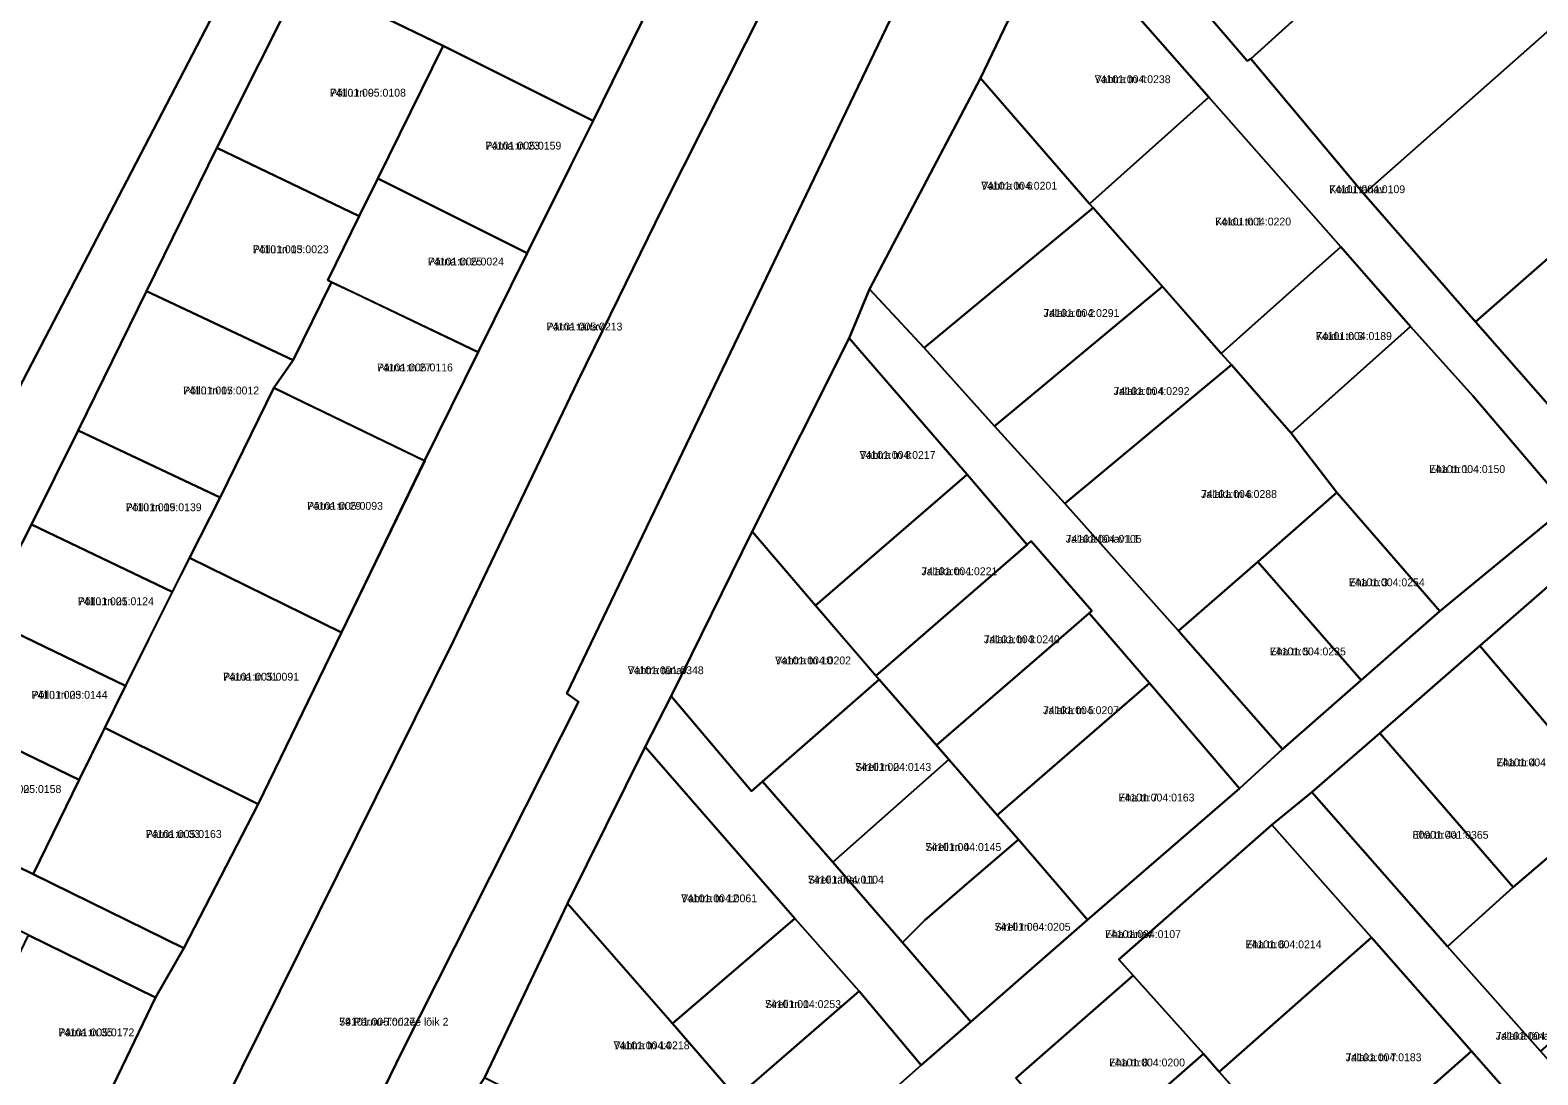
# Model space of a CAD drawing. Extents: x 524000 to 564260, y 6469338 to 6496391.
# Drawn here: x 537778.5 to 538066.5, y 6473057.4 to 6473256.9 of the extents above; entities that cross this region are included whole.
import ezdxf

# ---------------------------------------------------------------- set-up
doc = ezdxf.new("R2010")
doc.units = 0
for name, color, linetype in [('L_AADRESS', 7, 'Continuous'), ('PIIR', 7, 'Continuous'), ('TUNNUS', 7, 'Continuous')]:
    doc.layers.add(name, color=color, linetype=linetype)

msp = doc.modelspace()

# ---------------------------------------------------------------- linework, layer by layer
at = {"layer": 'PIIR'}
for points in [[(537911.45, 6473432.19), (537898.77, 6473405), (537878.24, 6473363.63), (537862.56, 6473331.9), (537846.66, 6473299.16), (537830.46, 6473267.01), (537814.16, 6473234.46), (537800.74, 6473207.08), (537787.69, 6473180.48), (537778.82, 6473162.48), (537769.71, 6473144.74), (537760.91, 6473126.77), (537752.14, 6473108.89), (537735.25, 6473107.1), (537744.18, 6473124.88), (537753.17, 6473143.42), (537772.14, 6473180.53), (537824.43, 6473280.98), (537842.16, 6473316.83), (537846.14, 6473325.5), (537858.94, 6473351.56), (537867.79, 6473369.49), (537901.08, 6473436.32)], [(537726.44, 6473156.95), (537699.68, 6473170.07), (537672.88, 6473183.77), (537646.08, 6473197.47), (537632.7, 6473204.36), (537624, 6473208.76), (537627.57, 6473215.35), (537724.12, 6473330.67), (537771.55, 6473307.16), (537797.54, 6473294.29), (537824.43, 6473280.98), (537772.14, 6473180.53), (537745.72, 6473193.99)], [(538037.45, 6473274.84), (538066.93, 6473300.55), (538088.99, 6473274.96), (538033.3, 6473225.67), (538011.66, 6473251.45)], [(537830.46, 6473267.01), (537846.66, 6473299.16), (537874.47, 6473287.9), (537902.82, 6473273.77), (537886.07, 6473239.61), (537857.45, 6473253.92)], [(538019.43, 6473296.1), (538037.45, 6473274.84), (538011.66, 6473251.45), (538011.01, 6473251.05), (537992.9, 6473272.24)], [(537979.58, 6473287.68), (537992.9, 6473272.24), (538011.01, 6473251.05), (538011.66, 6473251.45), (538033.3, 6473225.67), (538054.58, 6473201.22), (538079, 6473173.43), (538072.12, 6473165.95), (538054.09, 6473187.1), (538042.21, 6473200.34), (538028.86, 6473215.53), (538003.68, 6473244.12), (537974.33, 6473277.57)], [(537974.33, 6473277.57), (538003.68, 6473244.12), (537980.89, 6473223.78), (537960.04, 6473247.79)], [(538033.3, 6473225.67), (538088.99, 6473274.96), (538110.95, 6473250.31), (538070.39, 6473215.01), (538054.58, 6473201.22)], [(537830.46, 6473267.01), (537857.45, 6473253.92), (537844.93, 6473228.59), (537841.38, 6473221.39), (537814.16, 6473234.46)], [(537857.45, 6473253.92), (537886.07, 6473239.61), (537881.82, 6473231.11), (537873.44, 6473214.34), (537844.93, 6473228.59), (537853.2, 6473245.42)], [(537938.83, 6473207.45), (537960.04, 6473247.79), (537980.89, 6473223.78), (537981.55, 6473223.02), (537949.29, 6473196.28)], [(538006.05, 6473195.17), (537981.55, 6473223.02), (537980.89, 6473223.78), (538003.68, 6473244.12), (538028.86, 6473215.53)], [(537814.16, 6473234.46), (537841.38, 6473221.39), (537835.4, 6473209.21), (537836.11, 6473208.82), (537828.75, 6473193.88), (537800.74, 6473207.08)], [(537844.93, 6473228.59), (537873.44, 6473214.34), (537864.09, 6473195.4), (537836.11, 6473208.82), (537835.4, 6473209.21), (537841.38, 6473221.39)], [(537949.29, 6473196.28), (537981.55, 6473223.02), (537994.79, 6473207.97), (537962.73, 6473181.28)], [(538007.97, 6473192.99), (538006.05, 6473195.17), (538028.86, 6473215.53), (538042.21, 6473200.34), (538019.42, 6473179.98)], [(538054.58, 6473201.22), (538070.39, 6473215.01), (538088.51, 6473194.4), (538094.86, 6473187.09), (538079, 6473173.43)], [(537828.75, 6473193.88), (537836.11, 6473208.82), (537840.71, 6473206.61), (537864.09, 6473195.4), (537853.88, 6473174.7), (537830.42, 6473186.01), (537825.07, 6473188.59)], [(537938.83, 6473207.45), (537949.29, 6473196.28), (537962.73, 6473181.28), (537976.14, 6473166.52), (537997.9, 6473142.17), (538017.73, 6473119.59), (538009.53, 6473112.11), (537992.33, 6473132.2), (537980.78, 6473145.55), (537981.35, 6473146.04), (537969.75, 6473159.33), (537968.97, 6473158.65), (537957.48, 6473172.04), (537934.96, 6473198.12)], [(537976.14, 6473166.52), (537962.73, 6473181.28), (537994.79, 6473207.97), (538006.05, 6473195.17), (538007.97, 6473192.99)], [(537800.74, 6473207.08), (537828.75, 6473193.88), (537825.07, 6473188.59), (537814.81, 6473167.64), (537787.69, 6473180.48)], [(538019.42, 6473179.98), (538042.21, 6473200.34), (538054.09, 6473187.1), (538072.12, 6473165.95), (538047.81, 6473145.97), (538028.1, 6473168.59)], [(537916.45, 6473161.14), (537934.96, 6473198.12), (537957.48, 6473172.04), (537928.57, 6473147.02)], [(537976.14, 6473166.52), (538007.97, 6473192.99), (538019.42, 6473179.98), (538028.1, 6473168.59), (538013.01, 6473155.36), (537997.9, 6473142.17)], [(537814.81, 6473167.64), (537825.07, 6473188.59), (537853.89, 6473174.69), (537837.99, 6473141.9), (537808.95, 6473156.13)], [(537588.67, 6473182.04), (537601.13, 6473175.67), (537614.54, 6473168.87), (537627.92, 6473161.97), (537654.72, 6473148.27), (537681.52, 6473134.57), (537708.32, 6473120.87), (537735.25, 6473107.1), (537752.14, 6473108.89), (537779.08, 6473095.69), (537807.87, 6473081.6), (537802.47, 6473072.14), (537778.25, 6473084.07), (537753.6, 6473096.21), (537713.66, 6473101.96), (537679.62, 6473119.33), (537647.7, 6473135.08), (537617.7, 6473150.13), (537593.3, 6473162.73), (537575.4, 6473171.96), (537586.01, 6473183.4)], [(537787.69, 6473180.48), (537814.81, 6473167.64), (537808.95, 6473156.13), (537805.67, 6473149.63), (537778.82, 6473162.48)], [(537928.57, 6473147.02), (537954.29, 6473169.28), (537957.48, 6473172.04), (537968.97, 6473158.65), (537965.78, 6473155.89), (537940.06, 6473133.63)], [(538028.1, 6473168.59), (538047.81, 6473145.97), (538032.77, 6473132.78), (538013.01, 6473155.36)], [(537778.82, 6473162.48), (537805.67, 6473149.63), (537796.72, 6473131.69), (537769.71, 6473144.74)], [(537900.95, 6473129.73), (537916.45, 6473161.14), (537928.57, 6473147.02), (537940.68, 6473132.91), (537916.31, 6473111.59)], [(537940.68, 6473132.91), (537940.06, 6473133.63), (537965.78, 6473155.89), (537969.75, 6473159.33), (537981.35, 6473146.04), (537977.38, 6473142.6), (537951.67, 6473120.33)], [(538084.04, 6473105.65), (538080.82, 6473109.44), (538055.45, 6473139.33), (538079.61, 6473160.41), (538102.7, 6473133.45), (538107.59, 6473127.24)], [(537808.95, 6473156.13), (537837.99, 6473141.9), (537822.07, 6473109.06), (537792.79, 6473123.66), (537796.72, 6473131.69)], [(538013.01, 6473155.36), (538032.77, 6473132.78), (538017.73, 6473119.59), (537997.9, 6473142.17)], [(537769.71, 6473144.74), (537796.72, 6473131.69), (537787.92, 6473113.72), (537760.91, 6473126.77)], [(537954, 6473117.61), (537951.67, 6473120.33), (537977.38, 6473142.6), (537980.78, 6473145.55), (537992.33, 6473132.2), (537988.93, 6473129.26), (537963.22, 6473107)], [(538036.36, 6473122.66), (538055.45, 6473139.33), (538080.82, 6473109.44), (538061.82, 6473093.25)], [(537918.43, 6473113.44), (537940.68, 6473132.91), (537952.76, 6473119.08), (537954, 6473117.61), (537931.84, 6473097.98)], [(537900.95, 6473129.73), (537916.31, 6473111.59), (537918.43, 6473113.44), (537931.84, 6473097.98), (537945.13, 6473082.69), (537958.22, 6473067.48), (537948.73, 6473059.24), (537936.86, 6473073.37), (537924.59, 6473087.22), (537895.98, 6473120.02)], [(537980.52, 6473087), (537967.32, 6473102.34), (537963.22, 6473107), (537992.33, 6473132.2), (538009.53, 6473112.11)], [(537760.91, 6473126.77), (537787.92, 6473113.72), (537779.08, 6473095.69), (537752.14, 6473108.89)], [(537787.92, 6473113.72), (537792.79, 6473123.66), (537822.07, 6473109.06), (537807.87, 6473081.6), (537779.08, 6473095.69)], [(538049.28, 6473081.9), (538023.36, 6473111.35), (538036.36, 6473122.66), (538061.82, 6473093.25)], [(537895.98, 6473120.02), (537924.59, 6473087.22), (537901.21, 6473067.16), (537881.16, 6473090.1)], [(537949.45, 6473086.93), (537945.13, 6473082.69), (537931.84, 6473097.98), (537954, 6473117.61), (537963.22, 6473107), (537967.32, 6473102.34), (537957.02, 6473093.46)], [(538023.36, 6473111.35), (538049.28, 6473081.9), (538067.02, 6473061.88), (538084.82, 6473041.79), (538101.22, 6473023.61), (538092.79, 6473017.72), (538072.92, 6473040.16), (538053.81, 6473061.92), (538034.77, 6473083.64), (538015.7, 6473105.17)], [(538067.02, 6473061.88), (538049.28, 6473081.9), (538061.82, 6473093.25), (538080.82, 6473109.44), (538084.04, 6473105.65), (538098.17, 6473089.18)], [(538002.62, 6473061.39), (537989.19, 6473076.36), (537986.5, 6473079.39), (538015.7, 6473105.17), (538034.77, 6473083.64), (538005.67, 6473057.95)], [(537945.13, 6473082.69), (537949.45, 6473086.93), (537957.02, 6473093.46), (537967.32, 6473102.34), (537980.52, 6473087), (537958.22, 6473067.48)], [(537865.31, 6473056.81), (537881.16, 6473090.1), (537901.21, 6473067.16), (537913.47, 6473053.06), (537914.66, 6473051.52), (537900.8, 6473039.14)], [(537901.21, 6473067.16), (537924.59, 6473087.22), (537936.86, 6473073.37), (537913.47, 6473053.06)], [(537765.37, 6473057.33), (537778.25, 6473084.07), (537802.47, 6473072.14), (537789.59, 6473045.41)], [(538024.81, 6473036.32), (538005.67, 6473057.95), (538034.77, 6473083.64), (538053.81, 6473061.92)], [(537966.8, 6473056.75), (537989.19, 6473076.36), (538002.62, 6473061.39), (537980.04, 6473041.61)], [(537948.73, 6473059.24), (537916.53, 6473030.7), (537900.8, 6473039.14), (537914.66, 6473051.52), (537913.47, 6473053.06), (537936.86, 6473073.37)], [(537980.04, 6473041.61), (538002.62, 6473061.39), (538005.67, 6473057.95), (538015.88, 6473046.41), (537992.93, 6473026.64)], [(538041.79, 6473017.16), (538024.81, 6473036.32), (538053.81, 6473061.92), (538072.92, 6473040.16), (538044.04, 6473014.64)]]:
    msp.add_lwpolyline(points, close=True, dxfattribs=at)
for points in [[(537956.46, 6473287.47), (537881.05, 6473130.21), (537883.27, 6473128.62), (537849.5, 6473061.8), (537774.4, 6472907.16)], [(537774.4, 6472907.16), (537849.5, 6473061.8), (537883.27, 6473128.62), (537881.05, 6473130.21), (537956.46, 6473287.47)], [(537974.33, 6473277.57), (537960.04, 6473247.79), (537938.83, 6473207.45), (537934.96, 6473198.12), (537916.45, 6473161.14), (537900.95, 6473129.73), (537895.98, 6473120.02), (537881.16, 6473090.1), (537865.31, 6473056.81), (537859.24, 6473047.61), (537850.59, 6473029.67), (537841.89, 6473011.54), (537834.25, 6472995.57), (537825.7, 6472977.65), (537817.2, 6472959.86), (537804.19, 6472932.78), (537806.63, 6472920.9)], [(537777.77, 6473022.03), (537789.59, 6473045.41), (537802.47, 6473072.14), (537807.87, 6473081.6), (537822.07, 6473109.06), (537837.99, 6473141.9), (537853.88, 6473174.7), (537864.09, 6473195.4), (537873.44, 6473214.34), (537886.07, 6473239.61), (537902.82, 6473273.77)], [(537758.2, 6472936.23), (537782.42, 6472985.19), (537790.56, 6473001.47), (537797.29, 6473015.04), (537826.2, 6473073.34), (537859.38, 6473140.3), (537883.17, 6473189.89), (537890.89, 6473205.72), (537899.34, 6473222.91), (537923.04, 6473270.09)], [(537923.04, 6473270.09), (537899.34, 6473222.91), (537890.89, 6473205.72), (537883.17, 6473189.89), (537859.38, 6473140.3), (537826.2, 6473073.34), (537797.29, 6473015.04), (537790.56, 6473001.47), (537782.42, 6472985.19), (537758.2, 6472936.23)], [(537916.53, 6473030.7), (537948.73, 6473059.24), (537958.22, 6473067.48), (537980.52, 6473087), (538009.53, 6473112.11), (538017.73, 6473119.59), (538032.77, 6473132.78), (538047.81, 6473145.97), (538072.12, 6473165.95)], [(538079.61, 6473160.41), (538055.45, 6473139.33), (538036.36, 6473122.66), (538023.36, 6473111.35), (538015.7, 6473105.17), (537986.5, 6473079.39), (537989.19, 6473076.36), (537966.8, 6473056.75)]]:
    msp.add_lwpolyline(points, dxfattribs=at)

# ---------------------------------------------------------------- texts
at = {"layer": 'L_AADRESS'}
for s, p in [('Vahtra tn 4', (537981.86, 6473246.82)), ('Põllu tn 9', (537835.8, 6473244.24)), ('Pärna tn 23', (537865.49, 6473234.13)), ('Vahtra tn 6', (537960.19, 6473226.47)), ('Koidu tänav', (538026.66, 6473225.8)), ('Koidu tn 1', (538004.88, 6473219.63)), ('Põllu tn 13', (537821.06, 6473214.33)), ('Pärna tn 25', (537854.52, 6473211.99)), ('Jalaka tn 2', (537972.09, 6473202.15)), ('Pärna tänav', (537877.16, 6473199.57)), ('Koidu tn 3', (538024.13, 6473197.76)), ('Pärna tn 27', (537844.78, 6473191.76)), ('Põllu tn 17', (537807.77, 6473187.36)), ('Jalaka tn 4', (537985.48, 6473187.24)), ('Vahtra tn 8', (537936.96, 6473175.04)), ('Eha tn 1', (538045.77, 6473172.34)), ('Jalaka tn 6', (538002.18, 6473167.58)), ('Põllu tn 19', (537796.79, 6473165.05)), ('Pärna tn 29', (537831.42, 6473165.32)), ('Jalaka tänav L1', (537976.34, 6473159.03)), ('Jalaka tn 1', (537948.77, 6473152.83)), ('Eha tn 3', (538030.41, 6473150.71)), ('Põllu tn 21', (537787.66, 6473147.09)), ('Jalaka tn 3', (537960.7, 6473139.83)), ('Eha tn 5', (538015.34, 6473137.51)), ('Vahtra tänav', (537892.68, 6473133.92)), ('Vahtra tn 10', (537920.82, 6473135.79)), ('Pärna tn 31', (537815.39, 6473132.68)), ('Põllu tn 23', (537778.81, 6473129.23)), ('Jalaka tn 5', (537972.01, 6473126.28)), ('Sireli tn 2', (537936.14, 6473115.45)), ('Eha tn 4', (538058.59, 6473116.31)), ('Põllu tn 25', (537769.99, 6473111.23)), ('Eha tn 7', (537986.43, 6473109.6)), ('Pärna tn 33', (537800.61, 6473102.63)), ('Eha tn 4a', (538042.59, 6473102.48)), ('Sireli tn 4', (537949.53, 6473100.15)), ('Sireli tänav L1', (537927.1, 6473093.92)), ('Vahtra tn 12', (537902.88, 6473090.35)), ('Sireli tn 6', (537962.76, 6473084.91)), ('Eha tänav', (537983.85, 6473083.51)), ('Eha tn 6', (538010.69, 6473081.56)), ('Sireli tn 1', (537918.91, 6473070.14)), ('Pärna tn 35', (537783.92, 6473064.74)), ('59 Pärnu-Tori tee lõik 2', (537837.58, 6473066.78)), ('Vahtra tn 14', (537889.98, 6473062.26)), ('Jalaka tänav L2', (538058.46, 6473064.08)), ('Eha tn 8', (537984.61, 6473058.99)), ('Jalaka tn 7', (538029.79, 6473059.98))]:
    msp.add_text(s, height=1.5, dxfattribs=at).set_placement(p)
at = {"layer": 'TUNNUS'}
for s, p in [('74101:004:0238', (537981.86, 6473246.82)), ('74101:005:0108', (537835.8, 6473244.24)), ('74101:005:0159', (537865.49, 6473234.13)), ('74101:004:0201', (537960.19, 6473226.47)), ('74101:004:0109', (538026.66, 6473225.8)), ('74101:004:0220', (538004.88, 6473219.63)), ('74101:005:0023', (537821.06, 6473214.33)), ('74101:005:0024', (537854.52, 6473211.99)), ('74101:004:0291', (537972.09, 6473202.15)), ('74101:005:0213', (537877.16, 6473199.57)), ('74101:004:0189', (538024.13, 6473197.76)), ('74101:005:0116', (537844.78, 6473191.76)), ('74101:005:0012', (537807.77, 6473187.36)), ('74101:004:0292', (537985.48, 6473187.24)), ('74101:004:0217', (537936.96, 6473175.04)), ('74101:004:0150', (538045.77, 6473172.34)), ('74101:004:0288', (538002.18, 6473167.58)), ('74101:005:0139', (537796.79, 6473165.05)), ('74101:005:0093', (537831.42, 6473165.32)), ('74101:004:0105', (537976.34, 6473159.03)), ('74101:004:0221', (537948.77, 6473152.83)), ('74101:004:0254', (538030.41, 6473150.71)), ('74101:005:0124', (537787.66, 6473147.09)), ('74101:004:0240', (537960.7, 6473139.83)), ('74101:004:0235', (538015.34, 6473137.51)), ('74101:001:0348', (537892.68, 6473133.92)), ('74101:004:0202', (537920.82, 6473135.79)), ('74101:005:0091', (537815.39, 6473132.68)), ('74101:005:0144', (537778.81, 6473129.23)), ('74101:004:0207', (537972.01, 6473126.28)), ('74101:004:0143', (537936.14, 6473115.45)), ('74101:004:0165', (538058.59, 6473116.31)), ('74101:005:0158', (537769.99, 6473111.23)), ('74101:004:0163', (537986.43, 6473109.6)), ('74101:005:0163', (537800.61, 6473102.63)), ('80901:001:0365', (538042.59, 6473102.48)), ('74101:004:0145', (537949.53, 6473100.15)), ('74101:004:0104', (537927.1, 6473093.92)), ('74101:004:0061', (537902.88, 6473090.35)), ('74101:004:0205', (537962.76, 6473084.91)), ('74101:004:0107', (537983.85, 6473083.51)), ('74101:004:0214', (538010.69, 6473081.56)), ('74101:004:0253', (537918.91, 6473070.14)), ('74101:005:0172', (537783.92, 6473064.74)), ('74101:005:0027', (537837.58, 6473066.78)), ('74101:004:0218', (537889.98, 6473062.26)), ('74101:004:0108', (538058.46, 6473064.08)), ('74101:004:0200', (537984.61, 6473058.99)), ('74101:004:0183', (538029.79, 6473059.98))]:
    msp.add_text(s, height=1.5, dxfattribs=at).set_placement(p)

doc.saveas('drawing.dxf')
